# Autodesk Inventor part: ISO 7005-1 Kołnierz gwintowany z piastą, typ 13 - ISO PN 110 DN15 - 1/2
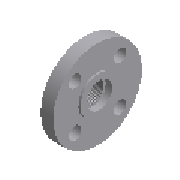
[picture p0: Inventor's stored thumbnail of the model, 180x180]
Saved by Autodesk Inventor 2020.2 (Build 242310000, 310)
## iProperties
Manager: www.cadconsulting.pl
Company: Fabian Stasiak CAD Consulting
Created: 2014-02
Part Number: ISO 7005-1 Kołnierz gwintowany z piastą, typ 13 - ISO PN 110 DN15 - 1/2
Material: Stal
Description: Kołnierze metalowe - Część 1: Kołnierze stalowe - Kołnierz gwintowany z piastą, typ 13 - ISO PN 110
Document SubType Name: Modeling
Standard: ISO 7005-1
Designer: F.Stasiak
Standard Revision: First edition 1992-04-15
Standards Organization: ISO
Language: pl-PL
Size Designation: DN15 - 1/2
Categories: <MemberInstance><Categories><Category DisplayName="Rury cienko- i grubościenne" InternalName="4347fa0f-2144-441d-94cd-e3e15c92b736" Mnemonic="TUBEANDPIPE"><Cate
Density: 1 g/cm^3
Appearance: Płyta
Catalog Web Link: www.expertbooks.pl
NAME: PIPING: ISO 7005-1 Hubbed Threaded Flange Type 13 - PN 110
DATA: <meta><inlinegroups number="1" deflen="1.8"></inlinegroups><connections number="2"></connections><angles><a>3.14159265358979</a></angles></meta>
IsCustomPart: 0
Author: F.Stasiak
Subject: Zbiór ćwiczeń. Autodesk Inventor 2020. Kurs Professional
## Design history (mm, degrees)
sketch "Sketch1"
  geometry: L1 (0, 0)-(22, 0) reference; L2 (0, 8.816)-(0, 17.5); L3 (0, 17.5)-(7, 17.5); L4 (7, 47.5)-(21.5, 47.5); L5 (0, 8.816)-(0, 0); L6 (7, 47.5)-(7, 17.5); L7 (21.5, 47.5)-(21.5, 19); L8 (21.5, 19)-(22, 19); L9 (22, 0)-(22, 12); L10 (22, 19)-(22, 12); L11 (16, 12)-(16, 9.316); L12 (16, 9.316)-(0, 8.816); L13 (16, 12)-(22, 12)
  constraints: 26 end point, 4 perpendicular, 3 parallel, 1 collinear, 1 horizontal
  dimensions: "d0" = 35 diameter of L3 L1 (= D1); "d1" = 95 diameter of L4 L1 (= D); "d2" = 38 diameter of L7.end L1 (= N2); "d3" = 7 distance between parallel lines of L2 L6 (= F2); "d9" = 24 diameter of L13 L1 (= V1); "d10" = 22 distance between parallel lines of L2 L10 (= H1); "d12" = 18.631 diameter of L11.end L1 (= MD); "d13" = 16 distance between parallel lines of L2 L11 (= T1); "d14" = 1.78991 deg angle of L1 L12; "d15" = 14.5 distance of L4.start L4.end (= C2)
revolve "Revolution1" stored, may be unused: angle "d11" = 90 deg
sketch "Sketch2"
  geometry: L1 (0, 0)-(0, 30.25); L2 (0, 0)-(21.39, 21.39); C1 r 17.5 at (0, 0) reference; C2 r 47.5 at (0, 0) reference; C3 r 8 at (21.39, 21.39); A1 r 30.25 centre (0, 0) between (0, 30.25) and (21.39, 21.39)
  constraints: 4 end point, 2 centre point, 2 coincident, 2 point on circle, 1 vertical
  dimensions: "d4" = 30.25 distance of L1.start L1.end (= 0.5 x K1); "d16" = 16 diameter of C3 (= L); "d17" = 45 deg angle of L2 L1 (computed from NU)
extrude "Extrusion1" cut sketch "Sketch2" distance "d5" = 14.5 (= C2); taper "d6" = 0 deg
pattern_circular "Circular Pattern1" dims angle "d8" = 360 deg
workaxis "Work Axis4"
workpoint "Work Point5"
workaxis "Work Axis5"
workpoint "Work Point6"
workaxis "Work Axis6"
workaxis "Work Axis7"
workpoint "Work Point7"
body "Solid1"
feature "Gwint1" dims "d122" = 10, "d123" = 0
other parameters: "C2" = 14.5 [user parameter; used in 2 equation terms], "D" = 95 [user parameter; used in 1 equation term], "K1" = 60.5 [user parameter; used in 1 equation term], "L" = 16 [user parameter; used in 1 equation term], "N2" = 38 [user parameter; used in 1 equation term], "D1" = 35 [user parameter; used in 1 equation term], "H1" = 22 [user parameter; used in 1 equation term], "F2" = 7 [user parameter; used in 1 equation term], "MD" = 18.631 [user parameter; used in 1 equation term], "T1" = 16 [user parameter; used in 1 equation term], "V1" = 24 [user parameter; used in 1 equation term], "Size_Designation" = 12.345 [user parameter]
